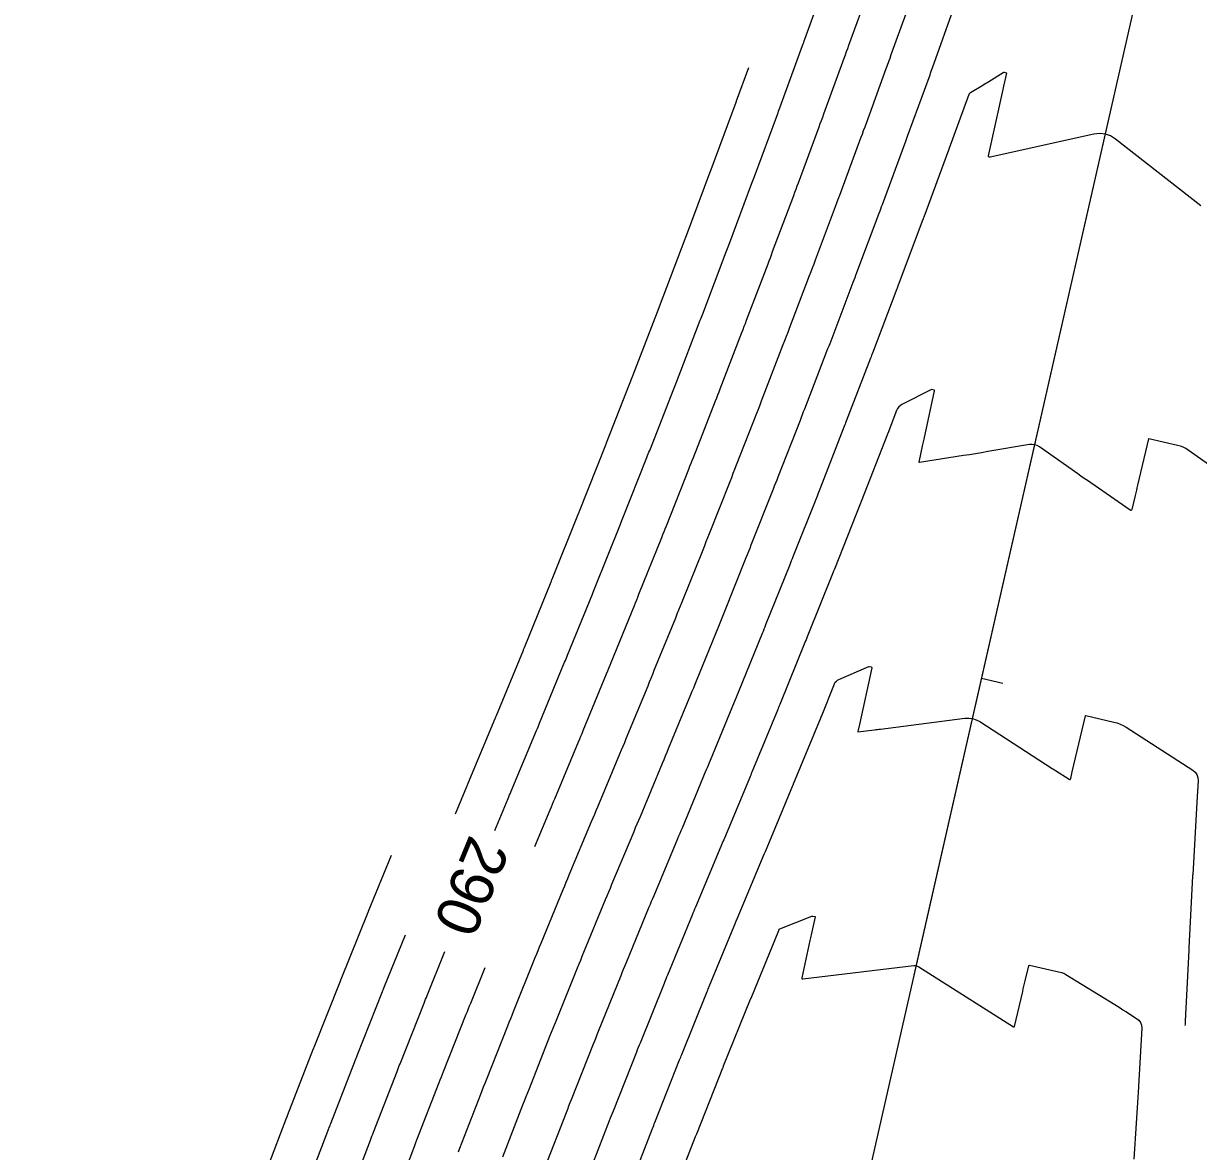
# Model space of a CAD drawing. Extents: x 1710723 to 1713003, y 548603 to 551142.
# Drawn here: x 1712246.8 to 1712408.5, y 550142.9 to 550298.2 of the extents above; entities that cross this region are included whole.
import ezdxf

# ---------------------------------------------------------------- set-up
doc = ezdxf.new("R2010")
doc.units = 0
for name, color, linetype in [('R_Contour Annot', 7, 'Continuous'), ('R_Contours', 7, 'Continuous'), ('R_Horz Alg', 7, 'Continuous'), ('R_Horz Alg Annot', 7, 'Continuous'), ('R_Striping', 7, 'Continuous')]:
    doc.layers.add(name, color=color, linetype=linetype)

msp = doc.modelspace()

# ---------------------------------------------------------------- linework, layer by layer
at = {"layer": 'R_Contours'}
for points in [[(1712311.63, 550187.07), (1712313.48, 550191.48), (1712313.58, 550191.73), (1712313.68, 550191.97), (1712313.79, 550192.22), (1712313.89, 550192.47), (1712317.39, 550200.85), (1712317.49, 550201.1), (1712317.59, 550201.34), (1712317.69, 550201.59), (1712317.79, 550201.83), (1712321.25, 550210.24), (1712321.35, 550210.48), (1712321.45, 550210.72), (1712321.55, 550210.96), (1712321.65, 550211.2), (1712325.07, 550219.63), (1712325.17, 550219.87), (1712325.27, 550220.11), (1712325.36, 550220.35), (1712325.46, 550220.59), (1712328.85, 550229.03), (1712328.94, 550229.27), (1712329.04, 550229.51), (1712329.13, 550229.74), (1712329.23, 550229.98), (1712332.57, 550238.44), (1712332.67, 550238.68), (1712332.76, 550238.92), (1712332.85, 550239.15), (1712332.95, 550239.39), (1712336.26, 550247.87), (1712336.35, 550248.1), (1712336.44, 550248.33), (1712336.53, 550248.57), (1712336.62, 550248.8), (1712339.9, 550257.31), (1712339.98, 550257.53), (1712340.07, 550257.76), (1712340.16, 550257.99), (1712340.25, 550258.22), (1712343.49, 550266.75), (1712343.58, 550266.98), (1712343.66, 550267.2), (1712343.75, 550267.43), (1712343.83, 550267.66), (1712347.03, 550276.2), (1712347.12, 550276.43), (1712347.2, 550276.65), (1712347.29, 550276.88), (1712347.37, 550277.11), (1712350.53, 550285.66), (1712350.62, 550285.88), (1712350.7, 550286.11), (1712350.78, 550286.34), (1712350.87, 550286.57), (1712353.99, 550295.15), (1712354.07, 550295.37), (1712354.15, 550295.58), (1712354.23, 550295.8), (1712354.31, 550296.02), (1712357.41, 550304.65)], [(1712363.09, 550302.83), (1712360.33, 550295.16), (1712360.17, 550294.71), (1712360, 550294.26), (1712359.84, 550293.81), (1712359.68, 550293.36), (1712356.88, 550285.68), (1712356.72, 550285.23), (1712356.55, 550284.79), (1712356.39, 550284.34), (1712356.22, 550283.89), (1712353.38, 550276.19), (1712353.22, 550275.76), (1712353.05, 550275.33), (1712352.89, 550274.89), (1712352.73, 550274.46), (1712349.83, 550266.72), (1712349.67, 550266.3), (1712349.51, 550265.87), (1712349.35, 550265.45), (1712349.19, 550265.03), (1712346.24, 550257.27), (1712346.08, 550256.85), (1712345.92, 550256.44), (1712345.76, 550256.02), (1712345.6, 550255.6), (1712342.61, 550247.83), (1712342.45, 550247.42), (1712342.29, 550247.01), (1712342.13, 550246.6), (1712341.97, 550246.19), (1712338.93, 550238.39), (1712338.77, 550237.99), (1712338.61, 550237.59), (1712338.45, 550237.18), (1712338.29, 550236.78), (1712335.2, 550228.97), (1712335.05, 550228.58), (1712334.89, 550228.18), (1712334.73, 550227.78), (1712334.57, 550227.38), (1712331.43, 550219.56), (1712331.28, 550219.17), (1712331.12, 550218.78), (1712330.96, 550218.39), (1712330.8, 550218), (1712327.62, 550210.16), (1712327.46, 550209.78), (1712327.3, 550209.39), (1712327.14, 550209), (1712326.98, 550208.62), (1712323.76, 550200.78), (1712323.6, 550200.4), (1712323.44, 550200.01), (1712323.28, 550199.63), (1712323.12, 550199.25), (1712319.85, 550191.4), (1712319.69, 550191.02), (1712319.54, 550190.65), (1712319.38, 550190.27), (1712319.22, 550189.89), (1712317.1, 550184.82)], [(1712306.62, 550142.84), (1712306.81, 550143.33), (1712309.71, 550150.78), (1712309.9, 550151.28), (1712310.09, 550151.77), (1712310.29, 550152.27), (1712310.48, 550152.76), (1712313.42, 550160.19), (1712313.62, 550160.68), (1712313.82, 550161.18), (1712314.02, 550161.67), (1712314.22, 550162.17), (1712317.21, 550169.58), (1712317.41, 550170.08), (1712317.61, 550170.57), (1712317.81, 550171.07), (1712318.02, 550171.57), (1712321.05, 550178.95), (1712321.26, 550179.45), (1712321.47, 550179.95), (1712321.68, 550180.45), (1712321.89, 550180.96), (1712324.96, 550188.3), (1712325.17, 550188.81), (1712325.39, 550189.32), (1712325.6, 550189.83), (1712325.81, 550190.34), (1712328.86, 550197.64), (1712329.08, 550198.16), (1712329.29, 550198.68), (1712329.51, 550199.2), (1712329.72, 550199.73), (1712332.72, 550207), (1712332.94, 550207.53), (1712333.15, 550208.06), (1712333.37, 550208.59), (1712333.59, 550209.13), (1712336.53, 550216.36), (1712336.75, 550216.91), (1712336.97, 550217.45), (1712337.19, 550217.99), (1712337.41, 550218.54), (1712340.29, 550225.73), (1712340.52, 550226.29), (1712340.74, 550226.85), (1712340.96, 550227.41), (1712341.18, 550227.96), (1712344.01, 550235.11), (1712344.24, 550235.69), (1712344.46, 550236.26), (1712344.69, 550236.83), (1712344.91, 550237.4), (1712347.69, 550244.52), (1712347.92, 550245.1), (1712348.14, 550245.68), (1712348.36, 550246.25), (1712348.59, 550246.83), (1712351.34, 550253.99), (1712351.56, 550254.55), (1712351.78, 550255.11), (1712351.99, 550255.67), (1712352.2, 550256.23), (1712354.95, 550263.47), (1712355.16, 550264.01), (1712355.36, 550264.55), (1712355.57, 550265.09), (1712355.77, 550265.63), (1712358.52, 550272.96), (1712358.71, 550273.48), (1712358.91, 550274), (1712359.1, 550274.52), (1712359.29, 550275.03), (1712362.03, 550282.45), (1712362.22, 550282.95), (1712362.4, 550283.46), (1712362.59, 550283.96), (1712362.77, 550284.46), (1712365.5, 550291.96), (1712365.68, 550292.44), (1712365.85, 550292.93), (1712366.03, 550293.41), (1712366.2, 550293.9), (1712368.93, 550301.48)], [(1712312.73, 550142.16), (1712315.5, 550149.31), (1712315.72, 550149.88), (1712315.94, 550150.44), (1712316.17, 550151.01), (1712316.39, 550151.57), (1712319.23, 550158.74), (1712319.45, 550159.3), (1712319.67, 550159.85), (1712319.89, 550160.41), (1712320.12, 550160.96), (1712323.02, 550168.16), (1712323.24, 550168.7), (1712323.46, 550169.24), (1712323.68, 550169.79), (1712323.91, 550170.33), (1712326.88, 550177.56), (1712327.1, 550178.09), (1712327.32, 550178.62), (1712327.54, 550179.15), (1712327.76, 550179.68), (1712330.81, 550186.96), (1712331.02, 550187.48), (1712331.24, 550187.99), (1712331.45, 550188.5), (1712331.67, 550189.01), (1712334.73, 550196.36), (1712334.94, 550196.86), (1712335.14, 550197.36), (1712335.35, 550197.85), (1712335.55, 550198.35), (1712338.61, 550205.78), (1712338.81, 550206.26), (1712339.01, 550206.73), (1712339.2, 550207.21), (1712339.39, 550207.69), (1712342.45, 550215.21), (1712342.64, 550215.66), (1712342.82, 550216.12), (1712343, 550216.58), (1712343.19, 550217.04), (1712346.24, 550224.65), (1712346.42, 550225.08), (1712346.59, 550225.52), (1712346.76, 550225.96), (1712346.94, 550226.39), (1712349.99, 550234.1), (1712350.15, 550234.51), (1712350.31, 550234.93), (1712350.48, 550235.34), (1712350.64, 550235.76), (1712353.69, 550243.57), (1712353.84, 550243.96), (1712353.99, 550244.35), (1712354.14, 550244.74), (1712354.3, 550245.13), (1712357.35, 550253.05), (1712357.49, 550253.41), (1712357.63, 550253.78), (1712357.77, 550254.14), (1712357.91, 550254.51), (1712360.96, 550262.55), (1712361.09, 550262.88), (1712361.22, 550263.22), (1712361.34, 550263.55), (1712361.47, 550263.89), (1712364.53, 550272.06), (1712364.65, 550272.37), (1712364.76, 550272.67), (1712364.87, 550272.97), (1712364.98, 550273.27), (1712368.06, 550281.59), (1712368.16, 550281.86), (1712368.26, 550282.13), (1712368.35, 550282.4), (1712368.45, 550282.67), (1712371.53, 550291.12), (1712371.62, 550291.36), (1712371.71, 550291.6), (1712371.79, 550291.84), (1712371.88, 550292.07), (1712374.97, 550300.68)], [(1712346.54, 550292.09), (1712344.86, 550287.47), (1712344.84, 550287.43), (1712344.8, 550287.32), (1712341.37, 550278.02), (1712341.35, 550277.98), (1712341.34, 550277.94), (1712337.83, 550268.59), (1712337.82, 550268.56), (1712337.81, 550268.53), (1712337.8, 550268.5), (1712337.79, 550268.47), (1712334.25, 550259.18), (1712334.24, 550259.14), (1712334.22, 550259.09), (1712334.2, 550259.05), (1712334.19, 550259.01), (1712330.63, 550249.78), (1712330.61, 550249.72), (1712330.59, 550249.66), (1712330.57, 550249.61), (1712330.54, 550249.55), (1712326.96, 550240.38), (1712326.94, 550240.31), (1712326.91, 550240.24), (1712326.88, 550240.18), (1712326.86, 550240.11), (1712323.25, 550230.99), (1712323.22, 550230.91), (1712323.18, 550230.83), (1712323.15, 550230.76), (1712323.12, 550230.68), (1712319.49, 550221.61), (1712319.45, 550221.52), (1712319.41, 550221.44), (1712319.38, 550221.35), (1712319.34, 550221.26), (1712315.68, 550212.24), (1712315.64, 550212.14), (1712315.6, 550212.05), (1712315.56, 550211.95), (1712315.52, 550211.86), (1712311.83, 550202.88), (1712311.78, 550202.78), (1712311.74, 550202.67), (1712311.69, 550202.56), (1712311.65, 550202.46), (1712307.93, 550193.53), (1712307.88, 550193.42), (1712307.83, 550193.3), (1712307.78, 550193.19), (1712307.74, 550193.07), (1712306.17, 550189.32)], [(1712408.79, 550273.08), (1712397.07, 550282.27), (1712396.38, 550282.71), (1712395.66, 550282.96), (1712394.9, 550283.04), (1712394.09, 550282.95), (1712379.8, 550279.78), (1712379.69, 550279.77), (1712379.62, 550279.8), (1712379.59, 550279.87), (1712379.6, 550279.97), (1712381.61, 550289.11), (1712381.66, 550289.34), (1712381.71, 550289.56), (1712382.09, 550291.32), (1712382.09, 550291.33), (1712382.09, 550291.34), (1712382.08, 550291.34), (1712382.08, 550291.34), (1712381.77, 550291.41), (1712381.73, 550291.42), (1712381.69, 550291.42), (1712381.65, 550291.41), (1712381.62, 550291.39), (1712379.61, 550290.15), (1712379.4, 550290.02), (1712379.2, 550289.9), (1712379, 550289.78), (1712378.79, 550289.65), (1712377.09, 550288.65), (1712377.02, 550288.6), (1712376.96, 550288.54), (1712376.91, 550288.47), (1712376.87, 550288.39), (1712374.14, 550280.88), (1712374.12, 550280.84), (1712374.11, 550280.8), (1712374.09, 550280.76), (1712374.08, 550280.72), (1712370.67, 550271.51), (1712370.64, 550271.42), (1712370.61, 550271.34), (1712370.58, 550271.25), (1712370.55, 550271.17), (1712367.16, 550262.14), (1712367.12, 550262.02), (1712367.07, 550261.89), (1712367.02, 550261.76), (1712366.97, 550261.63), (1712363.61, 550252.78), (1712363.54, 550252.62), (1712363.48, 550252.45), (1712363.41, 550252.28), (1712363.35, 550252.11), (1712360, 550243.43), (1712359.92, 550243.22), (1712359.85, 550243.02), (1712359.77, 550242.82), (1712359.69, 550242.61), (1712356.35, 550234.08), (1712356.26, 550233.84), (1712356.17, 550233.6), (1712356.07, 550233.36), (1712355.98, 550233.12), (1712352.66, 550224.73), (1712352.55, 550224.46), (1712352.44, 550224.19), (1712352.33, 550223.92), (1712352.23, 550223.65), (1712348.91, 550215.39), (1712348.79, 550215.09), (1712348.67, 550214.79), (1712348.55, 550214.49), (1712348.43, 550214.2), (1712345.12, 550206.06), (1712344.99, 550205.73), (1712344.86, 550205.4), (1712344.72, 550205.08), (1712344.59, 550204.75), (1712341.29, 550196.73), (1712341.14, 550196.38), (1712341, 550196.03), (1712340.85, 550195.68), (1712340.7, 550195.32), (1712337.4, 550187.41), (1712337.25, 550187.03), (1712337.09, 550186.66), (1712336.93, 550186.28), (1712336.78, 550185.91), (1712333.5, 550178.09), (1712333.34, 550177.69), (1712333.17, 550177.29), (1712333.01, 550176.9), (1712332.84, 550176.5), (1712329.65, 550168.75), (1712329.48, 550168.33), (1712329.31, 550167.92), (1712329.14, 550167.5), (1712328.98, 550167.08), (1712325.87, 550159.39), (1712325.69, 550158.96), (1712325.52, 550158.52), (1712325.35, 550158.09), (1712325.18, 550157.65), (1712322.15, 550150.01), (1712321.97, 550149.56), (1712321.8, 550149.11), (1712321.62, 550148.67), (1712321.45, 550148.22), (1712318.49, 550140.61)], [(1712416.53, 550232.77), (1712407.07, 550239.45), (1712406.72, 550239.66), (1712406.36, 550239.85), (1712405.99, 550239.99), (1712405.6, 550240.1), (1712401.63, 550241), (1712401.62, 550241), (1712401.61, 550241), (1712401.6, 550240.99), (1712401.59, 550240.98), (1712400.1, 550234.63), (1712400.01, 550234.27), (1712399.93, 550233.92), (1712399.85, 550233.56), (1712399.76, 550233.2), (1712399.3, 550231.26), (1712399.27, 550231.18), (1712399.23, 550231.14), (1712399.17, 550231.14), (1712399.09, 550231.18), (1712393.66, 550234.93), (1712393.21, 550235.24), (1712392.76, 550235.55), (1712392.31, 550235.86), (1712391.86, 550236.18), (1712386.6, 550239.89), (1712386.28, 550240.07), (1712385.95, 550240.19), (1712385.6, 550240.23), (1712385.23, 550240.2), (1712379.48, 550239.23), (1712378.64, 550239.09), (1712377.8, 550238.95), (1712376.96, 550238.81), (1712376.12, 550238.68), (1712370.08, 550237.72), (1712370.05, 550237.72), (1712370.03, 550237.73), (1712370.02, 550237.75), (1712370.02, 550237.78), (1712370.55, 550240.21), (1712370.59, 550240.39), (1712370.63, 550240.57), (1712370.67, 550240.75), (1712370.71, 550240.93), (1712372.17, 550247.61), (1712372.17, 550247.65), (1712372.16, 550247.67), (1712372.14, 550247.69), (1712372.11, 550247.7), (1712371.8, 550247.77), (1712371.79, 550247.78), (1712371.78, 550247.78), (1712371.76, 550247.77), (1712371.75, 550247.77), (1712367.67, 550245.71), (1712367.43, 550245.56), (1712367.22, 550245.38), (1712367.06, 550245.16), (1712366.94, 550244.9), (1712365.71, 550241.73), (1712365.7, 550241.69), (1712365.68, 550241.65), (1712362.07, 550232.39), (1712362.04, 550232.33), (1712362.02, 550232.27), (1712361.99, 550232.21), (1712361.97, 550232.15), (1712358.37, 550223.07), (1712358.33, 550222.96), (1712358.29, 550222.86), (1712358.25, 550222.76), (1712358.21, 550222.66), (1712354.64, 550213.74), (1712354.58, 550213.6), (1712354.52, 550213.46), (1712354.47, 550213.33), (1712354.41, 550213.19), (1712350.85, 550204.42), (1712350.78, 550204.25), (1712350.71, 550204.08), (1712350.64, 550203.9), (1712350.57, 550203.73), (1712347.02, 550195.11), (1712346.93, 550194.9), (1712346.85, 550194.7), (1712346.76, 550194.49), (1712346.68, 550194.29), (1712343.14, 550185.8), (1712343.04, 550185.57), (1712342.94, 550185.33), (1712342.84, 550185.09), (1712342.74, 550184.86), (1712339.24, 550176.5), (1712339.13, 550176.23), (1712339.02, 550175.97), (1712338.91, 550175.7), (1712338.8, 550175.44), (1712335.4, 550167.17), (1712335.28, 550166.88), (1712335.16, 550166.59), (1712335.05, 550166.3), (1712334.93, 550166.01), (1712331.62, 550157.82), (1712331.5, 550157.5), (1712331.37, 550157.19), (1712331.25, 550156.88), (1712331.12, 550156.57), (1712327.91, 550148.44), (1712327.78, 550148.11), (1712327.65, 550147.78), (1712327.52, 550147.45), (1712327.39, 550147.12), (1712324.25, 550139.05)], [(1712330.02, 550137.5), (1712333.33, 550146.03), (1712333.41, 550146.24), (1712333.5, 550146.46), (1712333.58, 550146.67), (1712333.67, 550146.88), (1712337.07, 550155.49), (1712337.15, 550155.68), (1712337.22, 550155.86), (1712337.3, 550156.05), (1712337.38, 550156.24), (1712340.88, 550164.93), (1712340.95, 550165.1), (1712341.02, 550165.26), (1712341.08, 550165.42), (1712341.15, 550165.58), (1712344.76, 550174.37), (1712344.82, 550174.5), (1712344.87, 550174.64), (1712344.93, 550174.77), (1712344.98, 550174.9), (1712348.71, 550183.8), (1712348.75, 550183.9), (1712348.79, 550184), (1712348.84, 550184.1), (1712348.88, 550184.2), (1712352.65, 550193.25), (1712352.67, 550193.31), (1712352.7, 550193.37), (1712352.73, 550193.43), (1712352.75, 550193.49), (1712356.54, 550202.7), (1712356.56, 550202.75), (1712356.58, 550202.79), (1712358.4, 550207.28), (1712358.5, 550207.48), (1712358.64, 550207.64), (1712358.8, 550207.78), (1712358.99, 550207.88), (1712363.11, 550209.66), (1712363.11, 550209.66), (1712363.12, 550209.67), (1712363.13, 550209.67), (1712363.14, 550209.66), (1712363.45, 550209.59), (1712363.48, 550209.58), (1712363.5, 550209.56), (1712363.51, 550209.53), (1712363.51, 550209.49), (1712361.81, 550201.68), (1712361.77, 550201.5), (1712361.6, 550200.69), (1712361.6, 550200.68), (1712361.6, 550200.68), (1712361.61, 550200.67), (1712361.62, 550200.67), (1712363.88, 550200.94), (1712364.08, 550200.97), (1712364.29, 550200.99), (1712364.5, 550201.02), (1712364.7, 550201.04), (1712376.32, 550202.53), (1712376.86, 550202.55), (1712377.39, 550202.48), (1712377.89, 550202.32), (1712378.37, 550202.06), (1712388.32, 550195.63), (1712388.44, 550195.56), (1712388.55, 550195.48), (1712388.67, 550195.41), (1712388.79, 550195.33), (1712390.66, 550194.15), (1712390.74, 550194.11), (1712390.81, 550194.11), (1712390.87, 550194.16), (1712390.9, 550194.25), (1712391.01, 550194.69), (1712391.06, 550194.91), (1712391.11, 550195.13), (1712392.94, 550202.88), (1712392.95, 550202.89), (1712392.95, 550202.89), (1712392.96, 550202.89), (1712392.97, 550202.89), (1712396.84, 550202.01), (1712397.28, 550201.89), (1712397.71, 550201.73), (1712398.12, 550201.54), (1712398.52, 550201.31), (1712407.68, 550195.38), (1712408.02, 550195.1), (1712408.26, 550194.77), (1712408.39, 550194.38), (1712408.42, 550193.93), (1712408.24, 550191.04), (1712408.24, 550191), (1712408.24, 550190.99), (1712407.68, 550180.98), (1712407.67, 550180.93), (1712407.67, 550180.89), (1712407.67, 550180.84), (1712407.67, 550180.79), (1712407.16, 550170.91), (1712407.15, 550170.83), (1712407.15, 550170.75), (1712407.14, 550170.67), (1712407.14, 550170.59), (1712406.65, 550160.83), (1712406.65, 550160.72), (1712406.64, 550160.61), (1712406.63, 550160.5), (1712406.63, 550160.39), (1712406.62, 550160.21)], [(1712297.39, 550183.64), (1712294.21, 550175.91), (1712294.2, 550175.88), (1712294.16, 550175.77), (1712290.43, 550166.55), (1712290.42, 550166.52), (1712290.41, 550166.5), (1712290.4, 550166.47), (1712290.39, 550166.44), (1712286.72, 550157.18), (1712286.7, 550157.13), (1712286.68, 550157.09), (1712286.67, 550157.04), (1712286.65, 550157), (1712283.07, 550147.78), (1712283.05, 550147.72), (1712283.02, 550147.66), (1712283, 550147.61), (1712282.98, 550147.55), (1712279.49, 550138.37)], [(1712335.78, 550135.94), (1712339.27, 550144.94), (1712339.31, 550145.03), (1712339.35, 550145.13), (1712339.39, 550145.22), (1712339.42, 550145.32), (1712343.02, 550154.4), (1712343.05, 550154.47), (1712343.07, 550154.54), (1712343.1, 550154.6), (1712343.13, 550154.67), (1712346.84, 550163.86), (1712346.85, 550163.89), (1712346.87, 550163.93), (1712346.88, 550163.97), (1712346.9, 550164), (1712350.72, 550173.31), (1712350.73, 550173.32), (1712350.79, 550173.47), (1712350.8, 550173.49), (1712350.82, 550173.51), (1712350.84, 550173.53), (1712350.86, 550173.54), (1712355.25, 550175.28), (1712355.29, 550175.29), (1712355.32, 550175.3), (1712355.36, 550175.3), (1712355.39, 550175.29), (1712355.7, 550175.22), (1712355.71, 550175.22), (1712355.72, 550175.21), (1712355.72, 550175.2), (1712355.72, 550175.18), (1712355.18, 550172.71), (1712355.14, 550172.51), (1712355.1, 550172.32), (1712355.06, 550172.12), (1712355.01, 550171.93), (1712353.89, 550166.77), (1712353.89, 550166.71), (1712353.91, 550166.67), (1712353.95, 550166.65), (1712354.01, 550166.65), (1712369.32, 550168.47), (1712369.49, 550168.48), (1712369.66, 550168.45), (1712369.82, 550168.4), (1712369.97, 550168.32), (1712383.02, 550160.05), (1712383.06, 550160.03), (1712383.1, 550160.03), (1712383.13, 550160.05), (1712383.14, 550160.1), (1712384.29, 550164.93), (1712384.37, 550165.29), (1712384.46, 550165.65), (1712384.55, 550166.01), (1712384.63, 550166.37), (1712385.13, 550168.46), (1712385.14, 550168.49), (1712385.16, 550168.51), (1712385.18, 550168.52), (1712385.22, 550168.52), (1712389.61, 550167.52), (1712389.77, 550167.48), (1712389.93, 550167.42), (1712390.08, 550167.35), (1712390.22, 550167.27), (1712396.96, 550163.11), (1712397.34, 550162.87), (1712397.72, 550162.64), (1712398.09, 550162.4), (1712398.47, 550162.16), (1712399.97, 550161.21), (1712400.29, 550160.95), (1712400.52, 550160.63), (1712400.65, 550160.26), (1712400.67, 550159.85), (1712400.22, 550151.87), (1712400.22, 550151.84), (1712400.22, 550151.82), (1712400.22, 550151.79), (1712400.21, 550151.76), (1712399.59, 550141.82)], [(1712299.3, 550172.68), (1712296.38, 550165.45), (1712296.32, 550165.31), (1712296.26, 550165.17), (1712296.2, 550165.02), (1712296.15, 550164.88), (1712292.66, 550156.07), (1712292.6, 550155.91), (1712292.54, 550155.76), (1712292.47, 550155.6), (1712292.41, 550155.44), (1712289.01, 550146.67), (1712288.94, 550146.5), (1712288.88, 550146.33), (1712288.81, 550146.17), (1712288.75, 550146), (1712285.42, 550137.25)], [(1712291.35, 550136.13), (1712294.52, 550144.45), (1712294.62, 550144.73), (1712294.73, 550145.01), (1712294.83, 550145.28), (1712294.94, 550145.56), (1712298.18, 550153.89), (1712298.28, 550154.16), (1712298.39, 550154.43), (1712298.49, 550154.7), (1712298.6, 550154.97), (1712301.91, 550163.31), (1712302.01, 550163.58), (1712302.11, 550163.84), (1712302.22, 550164.1), (1712302.32, 550164.36), (1712304.77, 550170.43)], [(1712310.25, 550168.17), (1712308.27, 550163.26), (1712308.12, 550162.89), (1712307.97, 550162.51), (1712307.82, 550162.13), (1712307.66, 550161.75), (1712304.54, 550153.86), (1712304.39, 550153.48), (1712304.24, 550153.1), (1712304.09, 550152.72), (1712303.94, 550152.34), (1712300.88, 550144.44), (1712300.73, 550144.06), (1712300.58, 550143.68), (1712300.43, 550143.29), (1712300.29, 550142.91), (1712297.28, 550135.01)]]:
    msp.add_lwpolyline(points, dxfattribs=at)
at = {"layer": 'R_Horz Alg'}
msp.add_line((1712246.77, 549627.28), (1712450.81, 550525.82), dxfattribs=at)
at = {"layer": 'R_Horz Alg Annot'}
msp.add_lwpolyline([(1712381.56, 550207.32), (1712378.64, 550207.99)], dxfattribs=at)
at = {"layer": 'R_Striping'}
msp.add_line((1712369.36, 550167.14), (1712450.81, 550525.82), dxfattribs=at)

# ---------------------------------------------------------------- texts
at = {"layer": 'R_Contour Annot'}
msp.add_text('290', height=6, rotation=247.6054, dxfattribs=at).set_placement((1712308.23, 550186.68))

doc.saveas('drawing.dxf')
